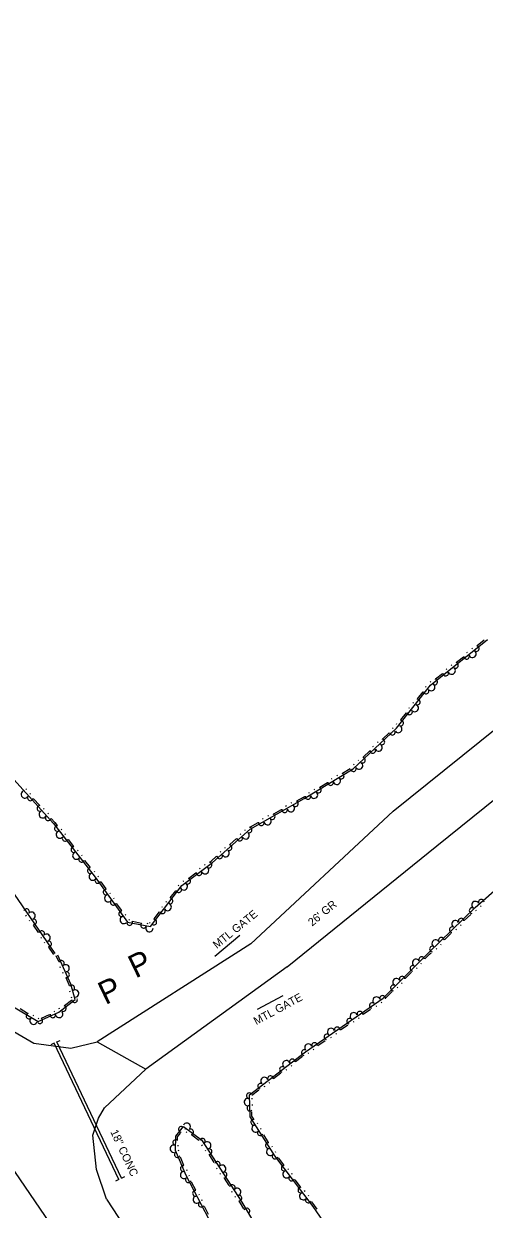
# Model space of a CAD drawing. Extents: x 2030130 to 2036320, y 723205 to 762423.
# Drawn here: x 2033765 to 2033977, y 760652 to 761198 of the extents above; entities that cross this region are included whole.
import ezdxf

# ---------------------------------------------------------------- set-up
doc = ezdxf.new("R2010")
doc.units = 0
for name, color, linetype in [('Draft_Station Labels Major', 7, 'Continuous'), ('Draft_Station Tics Major', 7, 'Continuous'), ('Draft_Station Tics Minor', 7, 'Continuous'), ('Exist Terrain Model Ground Surface', 7, 'Continuous'), ('Old_Level_23', 7, 'Continuous'), ('Old_Level_26', 7, 'Continuous'), ('Old_Level_28', 7, 'Continuous'), ('Prop Horizontal Alignment Ramp', 7, 'Continuous')]:
    doc.layers.add(name, color=color, linetype=linetype)

msp = doc.modelspace()

# ---------------------------------------------------------------- linework, layer by layer
at = {"layer": 'Draft_Station Labels Major'}
for p, q in [((2033869.46, 760774.27), (2033798.53, 760729.02)), ((2033886.15, 760763.66), (2033821, 760716.5)), ((2033752.56, 760738.09), (2033769.3, 760728.51)), ((2033769.3, 760728.51), (2033786.47, 760726.12)), ((2033786.47, 760726.12), (2033798.53, 760729.02)), ((2033798.53, 760729.02), (2033821, 760716.5)), ((2033802.89, 760656.57), (2033851.33, 760582.23))]:
    msp.add_line(p, q, dxfattribs=at)
for points in [[(2033869.46, 760774.27), (2033935.13, 760835.34), (2033990.71, 760880.07), (2034032.11, 760913.52), (2034058.88, 760935.52), (2034071.14, 760944.6), (2034079.83, 760951.72), (2034088.18, 760957.58), (2034094.76, 760962.04)], [(2033886.15, 760763.66), (2033955.13, 760819.42), (2034010.47, 760863.96), (2034051.97, 760897.49), (2034078.31, 760919.14), (2034090.56, 760928.21), (2034098.99, 760935.12), (2034106.37, 760940.3), (2034112.77, 760944.64)], [(2033718.38, 760730.67), (2033746.51, 760689.6), (2033774.62, 760648.49), (2033802.7, 760607.26), (2033830.67, 760566.06), (2033858.89, 760525.01), (2033886.8, 760483.79), (2033914.88, 760442.66), (2033945.45, 760397.69), (2033973.64, 760356.6), (2034001.68, 760315.42), (2034029.6, 760274.28), (2034057.68, 760233.24), (2034085.75, 760192.04), (2034113.77, 760150.87), (2034141.95, 760109.94), (2034159.83, 760083.11), (2034175.33, 760060.45), (2034197.95, 760027.35), (2034226.1, 759986.31), (2034253.95, 759945.01), (2034282.77, 759903.21), (2034311.52, 759860.74)], [(2033802.89, 760656.57), (2033798.24, 760670.25), (2033796.62, 760686.11), (2033799.16, 760693.82), (2033801.87, 760698.61), (2033821, 760716.5)]]:
    msp.add_lwpolyline(points, dxfattribs=at)
at = {"layer": 'Draft_Station Tics Major'}
for points in [[(2033418.93, 761226.23), (2033495.84, 761111.88), (2033561.64, 761018.79), (2033624.56, 760930.96), (2033696.62, 760828.37), (2033753.98, 760748.79), (2033771.32, 760738.45), (2033780.81, 760742.7), (2033788.33, 760748.62), (2033786.38, 760755.63), (2033780.42, 760769.02)], [(2033779.21, 760769.82), (2033754.79, 760805.41), (2033727.83, 760838.7), (2033706.75, 760866.89), (2033664.42, 760924.56), (2033636.24, 760963.58), (2033606.76, 761010.64), (2033581.36, 761049.61), (2033550.08, 761087.74), (2033512.77, 761135.79), (2033485.97, 761169.22), (2033454.96, 761209.86)], [(2033962.23, 760560.87), (2033948, 760582.67), (2033930.82, 760606.44), (2033914.22, 760629.94), (2033898.17, 760653.2), (2033880.46, 760676.52), (2033869.1, 760694.54), (2033868.73, 760704.66), (2033894.67, 760724.53), (2033930.48, 760749.27), (2033951.28, 760770.08), (2033972.88, 760790.96), (2033996.54, 760811.78), (2034033.52, 760843.01), (2034068.11, 760876.92), (2034094.26, 760902.79), (2034115.26, 760920)], [(2033753.09, 760857.73), (2033778.45, 760829.65), (2033797.68, 760805.05), (2033812.5, 760784.26), (2033823.08, 760782.2), (2033837.65, 760801.09), (2033851.68, 760811.77), (2033869.04, 760827.13), (2033894.06, 760841.19), (2033916.56, 760854.91), (2033936.62, 760873.6), (2033952.27, 760893.42), (2033978.62, 760914.55)], [(2033971.32, 760910.28), (2033971.64, 760910.54)], [(2033973.82, 760911.76), (2033977.02, 760914.32)], [(2033964.22, 760904.06), (2033967.42, 760906.62)], [(2033969.08, 760908.48), (2033969.4, 760908.74)], [(2033959.49, 760900.78), (2033959.81, 760901.04)], [(2033961.73, 760902.58), (2033962.05, 760902.84)], [(2033952.13, 760894.88), (2033952.45, 760895.14)], [(2033954.62, 760896.36), (2033957.82, 760898.92)], [(2033946.28, 760887.16), (2033948.82, 760890.37)], [(2033950.03, 760892.56), (2033950.28, 760892.88)], [(2033942.4, 760882.9), (2033942.65, 760883.23)], [(2033944.18, 760885.16), (2033944.43, 760885.48)], [(2033938.65, 760877.5), (2033941.19, 760880.72)], [(2033934.74, 760873.53), (2033935.04, 760873.81)], [(2033936.55, 760875.5), (2033936.8, 760875.83)], [(2033927.84, 760867.1), (2033928.14, 760867.38)], [(2033930.22, 760868.76), (2033933.22, 760871.56)], [(2033921.22, 760860.37), (2033924.22, 760863.17)], [(2033925.74, 760865.15), (2033926.04, 760865.43)], [(2033916.74, 760856.76), (2033917.04, 760857.04)], [(2033918.84, 760858.72), (2033919.14, 760858.99)], [(2033906.6, 760850.28), (2033906.95, 760850.49)], [(2033909.06, 760851.77), (2033909.41, 760851.99)], [(2033911.72, 760852.92), (2033915.22, 760855.05)], [(2033765.62, 760845.69), (2033765.9, 760845.39)], [(2033898.55, 760845.37), (2033898.9, 760845.58)], [(2033901.22, 760846.51), (2033904.72, 760848.65)], [(2033767.54, 760843.56), (2033767.82, 760843.26)], [(2033769.17, 760841.16), (2033771.91, 760838.11)], [(2033887.97, 760839.18), (2033888.33, 760839.38)], [(2033890.68, 760840.23), (2033893.65, 760841.89), (2033894.21, 760842.24)], [(2033896.1, 760843.87), (2033896.45, 760844.08)], [(2033773.87, 760836.56), (2033774.14, 760836.26)], [(2033775.79, 760834.43), (2033776.07, 760834.13)], [(2033879.95, 760834.2), (2033883.52, 760836.21)], [(2033885.47, 760837.77), (2033885.83, 760837.97)], [(2033777.41, 760832.03), (2033779.07, 760830.18), (2033780.11, 760828.86)], [(2033869.22, 760828.18), (2033872.8, 760830.18)], [(2033874.74, 760831.75), (2033875.1, 760831.95)], [(2033877.24, 760833.15), (2033877.6, 760833.35)], [(2033781.95, 760827.18), (2033782.2, 760826.85)], [(2033783.71, 760824.91), (2033783.97, 760824.59)], [(2033859.78, 760820.04), (2033862.85, 760822.76)], [(2033864.43, 760824.69), (2033864.73, 760824.96)], [(2033866.58, 760826.6), (2033866.88, 760826.87)], [(2033785.16, 760822.4), (2033787.69, 760819.17)], [(2033789.52, 760817.48), (2033789.78, 760817.16)], [(2033857.36, 760818.44), (2033857.67, 760818.71)], [(2033791.29, 760815.22), (2033791.55, 760814.9)], [(2033792.74, 760812.71), (2033795.26, 760809.48)], [(2033850.58, 760811.97), (2033851.16, 760812.41), (2033853.64, 760814.6)], [(2033855.21, 760816.54), (2033855.52, 760816.81)], [(2033797.1, 760807.79), (2033797.35, 760807.47)], [(2033840.79, 760804.52), (2033844.05, 760807)], [(2033845.76, 760808.81), (2033846.09, 760809.06)], [(2033848.05, 760810.55), (2033848.37, 760810.8)], [(2033798.89, 760805.48), (2033799.13, 760805.14)], [(2033800.22, 760802.9), (2033802.6, 760799.56)], [(2033835.96, 760800.92), (2033836.21, 760801.24)], [(2033838.26, 760803.1), (2033838.58, 760803.35)], [(2033804.37, 760797.8), (2033804.6, 760797.46)], [(2033806.03, 760795.46), (2033806.27, 760795.12)], [(2033832.28, 760795.47), (2033834.78, 760798.72)], [(2033807.37, 760792.88), (2033809.75, 760789.54)], [(2033828.45, 760791.17), (2033828.7, 760791.5)], [(2033830.2, 760793.45), (2033830.45, 760793.77)], [(2033973.17, 760789.54), (2033973.47, 760789.82)], [(2033975.26, 760791.42), (2033975.57, 760791.69)], [(2033765.89, 760787.05), (2033765.66, 760787.39)], [(2033767.52, 760784.68), (2033767.29, 760785.02)], [(2033811.51, 760787.78), (2033811.75, 760787.44)], [(2033813.18, 760785.44), (2033813.41, 760785.11)], [(2033814.92, 760784.63), (2033818.95, 760783.84)], [(2033824.77, 760785.73), (2033827.27, 760788.98)], [(2033967.87, 760784.99), (2033970.82, 760787.84)], [(2033771.57, 760779.5), (2033769.25, 760782.88)], [(2033821.44, 760783.77), (2033821.84, 760783.69)], [(2033822.69, 760783.7), (2033822.94, 760784.03)], [(2033958.73, 760776.15), (2033961.68, 760779)], [(2033964.03, 760780.7), (2033964.33, 760780.99)], [(2033966.09, 760782.7), (2033966.39, 760782.98)], [(2033772.86, 760776.9), (2033772.63, 760777.24)], [(2033774.48, 760774.54), (2033774.25, 760774.87)], [(2033956.96, 760773.86), (2033957.25, 760774.15)], [(2033778.53, 760769.36), (2033776.21, 760772.74)], [(2033780.85, 760766.03), (2033779.67, 760768.68)], [(2033949.64, 760767.28), (2033951.85, 760769.5), (2033952.54, 760770.16)], [(2033954.89, 760771.86), (2033955.18, 760772.15)], [(2033781.64, 760763.24), (2033781.48, 760763.62)], [(2033945.87, 760762.93), (2033946.16, 760763.22)], [(2033947.9, 760764.96), (2033948.19, 760765.26)], [(2033782.81, 760760.62), (2033782.65, 760760.99)], [(2033785.74, 760754.88), (2033785.61, 760755.36), (2033784.19, 760758.54)], [(2033940.65, 760758.29), (2033943.55, 760761.19)], [(2033786.11, 760752.01), (2033786, 760752.4)], [(2033931.67, 760749.3), (2033934.57, 760752.2)], [(2033936.88, 760753.94), (2033937.17, 760754.23)], [(2033938.92, 760755.97), (2033939.21, 760756.26)], [(2033783.44, 760745.81), (2033786.66, 760748.35)], [(2033786.88, 760749.24), (2033786.77, 760749.63)], [(2033929.53, 760747.11), (2033929.86, 760747.35)], [(2033762.97, 760744.39), (2033766.49, 760742.29)], [(2033768.81, 760741.38), (2033769.17, 760741.17)], [(2033772.89, 760740.05), (2033776.64, 760741.73)], [(2033778.72, 760743.11), (2033779.09, 760743.28)], [(2033780.94, 760744.36), (2033781.26, 760744.61)], [(2033921.19, 760741.86), (2033924.57, 760744.19)], [(2033927.16, 760745.48), (2033927.5, 760745.72)], [(2033771.28, 760739.91), (2033771.63, 760739.7)], [(2033910.74, 760734.63), (2033914.11, 760736.96)], [(2033916.71, 760738.25), (2033917.04, 760738.49)], [(2033919.06, 760739.89), (2033919.4, 760740.12)], [(2033900.28, 760727.4), (2033903.65, 760729.73)], [(2033906.25, 760731.03), (2033906.58, 760731.26)], [(2033908.61, 760732.66), (2033908.95, 760732.89)], [(2033898.15, 760725.43), (2033898.48, 760725.66)], [(2033890.04, 760719.94), (2033893.29, 760722.43)], [(2033895.79, 760723.8), (2033896.12, 760724.03)], [(2033879.94, 760712.21), (2033883.2, 760714.71)], [(2033885.73, 760716.13), (2033886.05, 760716.37)], [(2033888.01, 760717.87), (2033888.33, 760718.12)], [(2033875.63, 760708.4), (2033875.96, 760708.65)], [(2033877.91, 760710.14), (2033878.24, 760710.39)], [(2033869.85, 760704.48), (2033873.1, 760706.98)], [(2033870.03, 760702.62), (2033870.02, 760703.03)], [(2033870.14, 760699.75), (2033870.13, 760700.16)], [(2033870.76, 760693.45), (2033869.91, 760694.8), (2033869.84, 760696.87)], [(2033872.64, 760691.24), (2033872.42, 760691.59)], [(2033850.18, 760647.16), (2033839.63, 760667.37), (2033834.68, 760679.02), (2033834.79, 760685.59), (2033838.41, 760689.98), (2033846.7, 760683.86), (2033865.22, 760655.09), (2033891.74, 760610.39)], [(2033835.58, 760683.86), (2033835.6, 760685.29), (2033836.94, 760686.91)], [(2033839.08, 760688.86), (2033839.34, 760689.17)], [(2033839.64, 760687.55), (2033839.97, 760687.3)], [(2033842.19, 760686.17), (2033845.49, 760683.73)], [(2033874.17, 760688.81), (2033873.95, 760689.16)], [(2033877.54, 760682.69), (2033875.35, 760686.16)], [(2033835.94, 760680.98), (2033835.95, 760681.39)], [(2033846.73, 760681.54), (2033846.96, 760681.19)], [(2033879.41, 760680.48), (2033879.2, 760680.83)], [(2033836.16, 760678.68), (2033836, 760679.06)], [(2033838.51, 760672.1), (2033836.91, 760675.88)], [(2033848.29, 760679.12), (2033848.51, 760678.78)], [(2033850.19, 760676.93), (2033852.41, 760673.48)], [(2033880.94, 760678.06), (2033880.72, 760678.4)], [(2033884.7, 760672.29), (2033882.22, 760675.56)], [(2033840.01, 760669.62), (2033839.85, 760670)], [(2033853.61, 760670.85), (2033853.83, 760670.5)], [(2033886.76, 760670.25), (2033886.51, 760670.58)], [(2033841.15, 760667.1), (2033840.96, 760667.47)], [(2033844.02, 760660.73), (2033842.12, 760664.37)], [(2033855.17, 760668.43), (2033855.39, 760668.09)], [(2033857.07, 760666.24), (2033859.29, 760662.79)], [(2033888.5, 760667.97), (2033888.25, 760668.29)], [(2033892.39, 760662.17), (2033889.91, 760665.43)], [(2033845.71, 760658.38), (2033845.52, 760658.74)], [(2033860.49, 760660.16), (2033860.72, 760659.81)], [(2033894.45, 760660.13), (2033894.2, 760660.46)], [(2033847.04, 760655.83), (2033846.85, 760656.2)], [(2033862.05, 760657.74), (2033862.27, 760657.4)], [(2033863.95, 760655.55), (2033864.52, 760654.66), (2033866.06, 760652.07)], [(2033896.19, 760657.84), (2033895.94, 760658.17)], [(2033900.02, 760651.96), (2033898.83, 760653.69), (2033897.6, 760655.31)], [(2033849.9, 760649.46), (2033848, 760653.1)]]:
    msp.add_lwpolyline(points, dxfattribs=at)
for centre, radius, start, end in [((2033973.37, 760910.35), 1.3, 237.1723, 77.9689), ((2033968.89, 760906.75), 1.3, 179.5059, 20.3024), ((2033971.65, 760907.91), 1.69, 204.7011, 52.7736), ((2033959.3, 760899.05), 1.3, 179.5059, 20.3024), ((2033962.05, 760900.21), 1.69, 204.7011, 52.7736), ((2033963.77, 760902.65), 1.3, 237.1723, 77.9689), ((2033952.65, 760892.58), 1.69, 217.6556, 65.7281), ((2033954.18, 760894.95), 1.3, 237.1723, 77.9689), ((2033950.23, 760890.83), 1.3, 192.4603, 33.2569), ((2033945.02, 760882.92), 1.69, 217.6556, 65.7281), ((2033946.16, 760885.68), 1.3, 250.1268, 90.9234), ((2033938.53, 760876.03), 1.3, 250.1268, 90.9234), ((2033942.6, 760881.18), 1.3, 192.4603, 33.2569), ((2033934.68, 760871.8), 1.3, 183.7524, 24.549), ((2033937.4, 760873.27), 1.69, 217.6556, 65.7281), ((2033929.88, 760867.32), 1.3, 241.4189, 82.2155), ((2033925.68, 760863.41), 1.3, 183.7524, 24.549), ((2033928.34, 760864.76), 1.69, 208.9477, 57.0202), ((2033916.68, 760855.02), 1.3, 183.7524, 24.549), ((2033919.34, 760856.38), 1.69, 208.9477, 57.0202), ((2033920.88, 760858.93), 1.3, 241.4189, 82.2155), ((2033909.07, 760849.38), 1.69, 197.3471, 45.4196), ((2033911.1, 760851.58), 1.3, 229.8183, 70.6148), ((2033765.2, 760843.1), 1.69, 118.0477, 326.1202), ((2033900.59, 760845.17), 1.3, 229.8183, 70.6148), ((2033906.19, 760848.59), 1.3, 172.1518, 12.9484), ((2033767.73, 760841.52), 1.3, 150.5189, 351.3155), ((2033890, 760838.91), 1.3, 227.7548, 68.5514), ((2033895.69, 760842.18), 1.3, 172.1518, 12.9484), ((2033898.57, 760842.97), 1.69, 197.3471, 45.4196), ((2033772.13, 760836.65), 1.3, 92.8525, 293.649), ((2033773.44, 760833.97), 1.69, 118.0477, 326.1202), ((2033879.28, 760832.88), 1.3, 227.7548, 68.5514), ((2033885, 760836.1), 1.3, 170.0883, 10.8849), ((2033887.9, 760836.79), 1.69, 195.2836, 43.3561), ((2033775.98, 760832.39), 1.3, 150.5189, 351.3155), ((2033780.22, 760827.39), 1.3, 88.7872, 289.5838), ((2033874.27, 760830.07), 1.3, 170.0883, 10.8849), ((2033877.18, 760830.76), 1.69, 195.2836, 43.3561), ((2033781.34, 760824.62), 1.69, 113.9825, 322.055), ((2033783.76, 760822.86), 1.3, 146.4537, 347.2502), ((2033864.32, 760822.96), 1.3, 182.2759, 23.0724), ((2033867.01, 760824.25), 1.69, 207.4712, 55.5436), ((2033868.62, 760826.76), 1.3, 239.9423, 80.7389), ((2033787.8, 760817.69), 1.3, 88.7872, 289.5838), ((2033857.8, 760816.09), 1.69, 207.4712, 55.5436), ((2033859.41, 760818.61), 1.3, 239.9423, 80.7389), ((2033788.92, 760814.93), 1.69, 113.9825, 322.055), ((2033791.33, 760813.17), 1.3, 146.4537, 347.2502), ((2033850.1, 760810.57), 1.3, 235.703, 76.4995), ((2033855.11, 760814.8), 1.3, 182.2759, 23.0724), ((2033795.37, 760808), 1.3, 88.7872, 289.5838), ((2033796.5, 760805.24), 1.69, 113.9825, 322.055), ((2033845.53, 760807.09), 1.3, 178.0365, 18.8331), ((2033848.31, 760808.18), 1.69, 203.2318, 51.3043), ((2033798.84, 760803.43), 1.3, 143.9264, 344.723), ((2033838.52, 760800.73), 1.69, 203.2318, 51.3043), ((2033840.31, 760803.12), 1.3, 235.703, 76.4995), ((2033802.65, 760798.08), 1.3, 86.2599, 287.0565), ((2033803.65, 760795.27), 1.69, 111.4552, 319.5277), ((2033832.18, 760794), 1.3, 250.813, 91.6096), ((2033836.18, 760799.19), 1.3, 193.1466, 33.9431), ((2033765.98, 760789.1), 1.3, 322.897, 163.6936), ((2033805.98, 760793.41), 1.3, 143.9264, 344.723), ((2033828.67, 760789.45), 1.3, 193.1466, 33.9431), ((2033831.08, 760791.22), 1.69, 218.3418, 66.4143), ((2033971.43, 760789.57), 1.3, 62.4658, 263.2624), ((2033972.98, 760792.15), 1.69, 27.2979, 235.3704), ((2033975.68, 760793.43), 1.3, 2.1026, 202.8992), ((2033768.28, 760787.19), 1.69, 290.4258, 138.4983), ((2033769.23, 760784.36), 1.3, 265.2305, 106.0271), ((2033809.79, 760788.07), 1.3, 86.2599, 287.0565), ((2033810.79, 760785.25), 1.69, 111.4552, 319.5277), ((2033813.56, 760784.06), 1.3, 187.379, 28.1756), ((2033824.67, 760784.25), 1.3, 250.813, 91.6096), ((2033963.78, 760783.31), 1.69, 29.9946, 238.0671), ((2033966.42, 760784.72), 1.3, 4.7993, 205.5959), ((2033772.94, 760778.95), 1.3, 322.897, 163.6936), ((2033820, 760782.8), 1.3, 129.7125, 330.5091), ((2033822.66, 760781.44), 1.69, 154.9078, 2.9803), ((2033962.29, 760780.73), 1.3, 62.4658, 263.2624), ((2033775.24, 760777.05), 1.69, 290.4258, 138.4983), ((2033776.19, 760774.22), 1.3, 265.2305, 106.0271), ((2033954.64, 760774.48), 1.69, 29.9946, 238.0671), ((2033957.28, 760775.88), 1.3, 4.7993, 205.5959), ((2033948.19, 760766.99), 1.3, 5.7911, 206.5876), ((2033953.15, 760771.89), 1.3, 62.4658, 263.2624), ((2033782.1, 760765.24), 1.3, 312.4675, 153.264), ((2033784.02, 760762.95), 1.69, 279.9963, 128.0688), ((2033944.13, 760762.93), 1.3, 63.4575, 264.2541), ((2033945.58, 760765.54), 1.69, 30.9863, 239.0588), ((2033784.44, 760760), 1.3, 254.801, 95.5976), ((2033936.6, 760756.55), 1.69, 30.9863, 239.0588), ((2033939.2, 760758), 1.3, 5.7911, 206.5876), ((2033786.86, 760753.92), 1.3, 303.9528, 144.7494), ((2033788.42, 760751.37), 1.69, 271.4816, 119.5541), ((2033935.15, 760753.94), 1.3, 63.4575, 264.2541), ((2033788.14, 760748.47), 1.3, 179.0035, 19.8), ((2033925.45, 760745.8), 1.3, 53.082, 253.8786), ((2033927.35, 760748.1), 1.69, 20.6108, 228.6833), ((2033930.18, 760749.06), 1.3, 355.4156, 196.2121), ((2033767.13, 760740.96), 1.3, 109.9616, 310.7582), ((2033778.1, 760741.48), 1.3, 164.8563, 5.6528), ((2033781.05, 760741.9), 1.69, 190.0515, 38.124), ((2033782.98, 760744.41), 1.3, 236.6699, 77.4665), ((2033916.89, 760740.87), 1.69, 20.6108, 228.6833), ((2033919.72, 760741.83), 1.3, 355.4156, 196.2121), ((2033769.17, 760738.78), 1.69, 135.1569, 343.2294), ((2033772.1, 760738.8), 1.3, 222.5227, 63.3193), ((2033906.43, 760733.65), 1.69, 20.6108, 228.6833), ((2033909.26, 760734.6), 1.3, 355.4156, 196.2121), ((2033914.99, 760738.57), 1.3, 53.082, 253.8786), ((2033904.53, 760731.34), 1.3, 53.082, 253.8786), ((2033894.1, 760724.08), 1.3, 55.8781, 256.6746), ((2033895.97, 760726.42), 1.69, 20.6108, 228.6833), ((2033898.8, 760727.38), 1.3, 355.4156, 196.2121), ((2033885.78, 760718.75), 1.69, 23.4069, 231.4794), ((2033888.56, 760719.84), 1.3, 358.2116, 199.0082), ((2033878.47, 760712.12), 1.3, 358.2116, 199.0082), ((2033884, 760716.35), 1.3, 55.8781, 256.6746), ((2033873.91, 760708.62), 1.3, 55.8781, 256.6746), ((2033875.69, 760711.02), 1.69, 23.4069, 231.4794), ((2033868.03, 760701.31), 1.69, 78.0864, 286.1589), ((2033868.74, 760704.21), 1.3, 52.8911, 253.6877), ((2033868.96, 760698.47), 1.3, 110.5576, 311.3542), ((2033839.87, 760689.93), 1.69, 309.5346, 157.607), ((2033870.72, 760691.97), 1.3, 82.9764, 283.773), ((2033837.35, 760688.69), 1.3, 68.8589, 269.6555), ((2033841.69, 760687.56), 1.3, 284.3393, 125.1359), ((2033871.56, 760689.11), 1.69, 108.1717, 316.2441), ((2033873.78, 760687.11), 1.3, 140.6429, 341.4394), ((2033833.87, 760679.78), 1.69, 75.0202, 283.0927), ((2033834.74, 760682.64), 1.3, 49.825, 250.6215), ((2033847.1, 760683.24), 1.3, 321.1981, 161.9946), ((2033849.35, 760681.27), 1.69, 288.7269, 136.7994), ((2033877.5, 760681.22), 1.3, 82.9764, 283.773), ((2033835.51, 760677.07), 1.3, 131.4366, 332.2332), ((2033850.21, 760678.41), 1.3, 263.5316, 104.3282), ((2033878.33, 760678.35), 1.69, 108.1717, 316.2441), ((2033880.57, 760676.37), 1.3, 145.6538, 346.4504), ((2033838.23, 760670.65), 1.3, 73.7701, 274.5667), ((2033853.98, 760672.55), 1.3, 321.1981, 161.9946), ((2033856.23, 760670.58), 1.69, 288.7269, 136.7994), ((2033884.79, 760670.82), 1.3, 87.9873, 288.7839), ((2033885.87, 760668.03), 1.69, 113.1826, 321.2551), ((2033838.6, 760667.69), 1.69, 98.9654, 307.0379), ((2033840.63, 760665.44), 1.3, 136.0011, 336.7977), ((2033857.09, 760667.72), 1.3, 263.5316, 104.3282), ((2033888.26, 760666.24), 1.3, 145.6538, 346.4504), ((2033843.86, 760659.26), 1.3, 78.3346, 279.1312), ((2033860.86, 760661.86), 1.3, 321.1981, 161.9946), ((2033863.11, 760659.89), 1.69, 288.7269, 136.7994), ((2033892.48, 760660.69), 1.3, 87.9873, 288.7839), ((2033893.56, 760657.91), 1.69, 113.1826, 321.2551), ((2033844.46, 760656.34), 1.69, 103.5299, 311.6024), ((2033846.52, 760654.17), 1.3, 136.0011, 336.7977), ((2033863.97, 760657.03), 1.3, 263.5316, 104.3282), ((2033895.95, 760656.12), 1.3, 145.6538, 346.4504), ((2033867.6, 760651.08), 1.3, 319.1149, 159.9115)]:
    msp.add_arc(centre, radius, start, end, dxfattribs=at)
at = {"layer": 'Draft_Station Tics Minor'}
for p, q in [((2033780.02, 760729.01), (2033781.51, 760729.72)), ((2033778.69, 760728.38), (2033777.21, 760727.68)), ((2033808.48, 760665.6), (2033807, 760664.89)), ((2033809.81, 760666.23), (2033811.3, 760666.93))]:
    msp.add_line(p, q, dxfattribs=at)
for points in [[(2033808.48, 760665.6), (2033778.69, 760728.38)], [(2033809.81, 760666.23), (2033780.02, 760729.01)]]:
    msp.add_lwpolyline(points, dxfattribs=at)
at = {"layer": 'Exist Terrain Model Ground Surface'}
for p, q in [((2033852.87, 760768.54), (2033864.37, 760778.25)), ((2033872.49, 760744.09), (2033884.28, 760750.46))]:
    msp.add_line(p, q, dxfattribs=at)

# ---------------------------------------------------------------- texts
at = {"layer": 'Old_Level_23'}
msp.add_text("26' GR", height=3.691, rotation=39.5859, dxfattribs=at).set_placement((2033897.68, 760782.16))
at = {"layer": 'Old_Level_26'}
msp.add_text('18" CONC', height=3.691, rotation=294.964, dxfattribs=at).set_placement((2033804.53, 760687.58))
at = {"layer": 'Old_Level_28'}
for rotation, p in [(39.0456, (2033853.75, 760771.81)), (28.471, (2033871.92, 760736.72))]:
    msp.add_text('MTL GATE', height=3.691, rotation=rotation, dxfattribs=at).set_placement(p)
at = {"layer": 'Prop Horizontal Alignment Ramp'}
for p in [(2033816.23, 760758.19), (2033802.34, 760745.93)]:
    msp.add_text('P', height=10.66, rotation=25.7434, dxfattribs=at).set_placement(p)

doc.saveas('drawing.dxf')
